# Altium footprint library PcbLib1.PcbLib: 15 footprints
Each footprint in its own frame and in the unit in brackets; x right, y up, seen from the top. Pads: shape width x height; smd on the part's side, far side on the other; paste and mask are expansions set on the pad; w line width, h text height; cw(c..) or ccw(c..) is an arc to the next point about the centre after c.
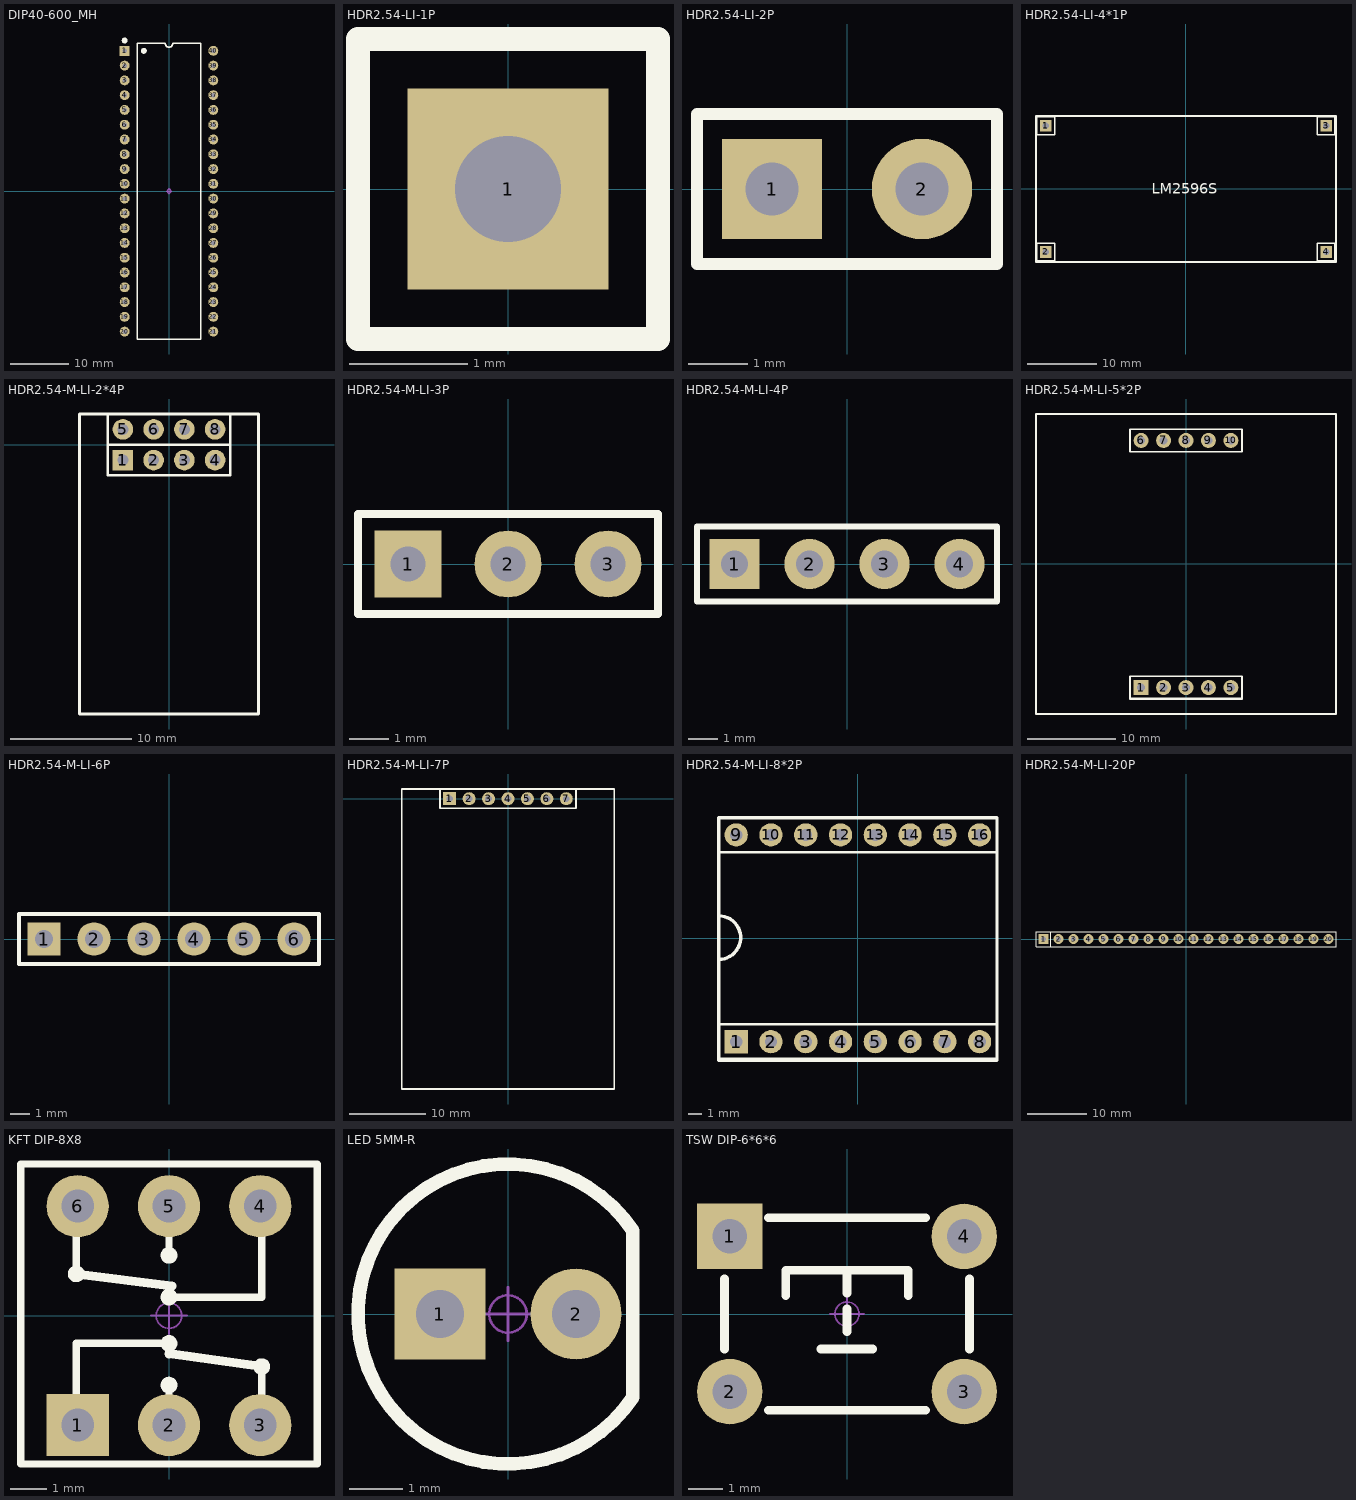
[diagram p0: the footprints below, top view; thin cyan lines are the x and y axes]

## DIP40-600_MH [mm] "带底座 52*15.2*4mm(长宽高)"
pads (40):
  rect 1.7x1.7 hole 0.8: 1(-7.62,24.13)
  round 1.7 hole 0.8: 2(-7.62,21.59) 3(-7.62,19.05) 4(-7.62,16.51) 5(-7.62,13.97) 6(-7.62,11.43) 7(-7.62,8.89) 8(-7.62,6.35) 9(-7.62,3.81) 10(-7.62,1.27) 11(-7.62,-1.27) 12(-7.62,-3.81) 13(-7.62,-6.35) 14(-7.62,-8.89) 15(-7.62,-11.43) 16(-7.62,-13.97) 17(-7.62,-16.51) 18(-7.62,-19.05) 19(-7.62,-21.59) 20(-7.62,-24.13) 21(7.62,-24.13) 22(7.62,-21.59) 23(7.62,-19.05) 24(7.62,-16.51) 25(7.62,-13.97) 26(7.62,-11.43) 27(7.62,-8.89) 28(7.62,-6.35) 29(7.62,-3.81) 30(7.62,-1.27) 31(7.62,1.27) 32(7.62,3.81) 33(7.62,6.35) 34(7.62,8.89) 35(7.62,11.43) 36(7.62,13.97) 37(7.62,16.51) 38(7.62,19.05) 39(7.62,21.59) 40(7.62,24.13)
Top Overlay:
  circle w0.508: c-4.318,24.13 r0.254
  circle w0.508: c-7.62,25.908 r0.254
  lines w0.254: -5.461,-25.4 5.461,-25.4 5.461,25.4 0.635,25.4 cw(c0,25.4) -0.635,25.4 -5.461,25.4 -5.461,-25.4
Mechanical 15:
  circle w0.05: c0,0 r0.35
  lines w0.05: -0.5,0 0.5,0 ; 0,-0.5 0,0.5
3D body "DIP-MH40-600.STEP": height 5.2, standoff -3, extent -8.9,-25.3 8.9,25.3
3D body "DIP40-600.STEP": height 8.3, standoff 0.4, extent -7.78,-26.176 7.78,26.176

## HDR2.54-LI-1P [mm] "封装库来自淘宝卖家 ID：黄晶宝石"
pads (1):
  rect 1.7x1.7 hole 0.9: 1(0,0)
Top Overlay:
  lines w0.2: -1.27,-1.27 -1.27,1.27 1.27,1.27 1.27,-1.27 -1.27,-1.27
3D body "HDR2.54-1P.STEP": height 8.5, standoff -3, extent -1.27,-1.27 1.27,1.27

## HDR2.54-LI-2P [mm] "封装库来自淘宝卖家 ID：黄晶宝石"
pads (2):
  rect 1.7x1.7 hole 0.9: 1(-1.27,0)
  round 1.7 hole 0.9: 2(1.27,0)
Top Overlay:
  lines w0.2: -2.54,-1.27 -2.54,1.27 2.54,1.27 2.54,-1.27 -2.54,-1.27
3D body "HDR2.54-1P.STEP": height 8.5, standoff -3, extent 0,-1.27 2.54,1.27
3D body "HDR2.54-1P.STEP": height 8.5, standoff -3, extent -2.54,-1.27 0,1.27

## HDR2.54-LI-4*1P [mm]
pads (4):
  rect 1.7x1.7 hole 0.9: 1(-20.193,9.08) 2(-20.193,-9.08) 3(20.193,9.08) 4(20.193,-9.08)
Top Overlay:
  lines w0.2: -21.463,-10.351 -18.923,-10.351 -18.923,-7.81 -21.463,-7.81 -21.463,-10.351 ; -21.463,7.81 -21.463,10.351 -18.923,10.351 -18.923,7.81 -21.463,7.81 ; 18.923,-10.351 21.463,-10.351 21.463,-7.81 18.923,-7.81 18.923,-10.351 ; 18.923,7.81 21.463,7.81 21.463,10.351 18.923,10.351 18.923,7.81
  lines w0.254: -21.59,-10.523 21.61,-10.523 21.61,10.477 -21.59,10.477 -21.59,-10.523
  text "LM2596S" at -4.953,-0.699 h1.52
3D body "HDR2.54-1P.STEP": height 8.5, standoff -3, extent 18.923,7.81 21.463,10.351
3D body "HDR2.54-1P.STEP": height 8.5, standoff -3, extent 18.923,-10.351 21.463,-7.81
3D body "HDR2.54-1P.STEP": height 8.5, standoff -3, extent -21.463,-10.351 -18.923,-7.81
3D body "HDR2.54-1P.STEP": height 8.5, standoff -3, extent -21.463,7.81 -18.923,10.351

## HDR2.54-M-LI-2*4P [mm]
pads (8):
  rect 1.7x1.7 hole 0.9: 1(-3.81,-1.27)
  round 1.7 hole 0.9: 2(-1.27,-1.27) 3(1.27,-1.27) 4(3.81,-1.27) 5(-3.81,1.27) 6(-1.27,1.27) 7(1.27,1.27) 8(3.81,1.27)
Top Overlay:
  lines w0.2: -5.08,0 5.08,0 ; -5.08,0 -5.08,2.54 5.08,2.54 5.08,0 ; -5.08,0 -5.08,-2.54 5.08,-2.54 5.08,0 ; -5.08,0 5.08,0
  lines w0.254: -7.4,-22.26 -7.4,2.54 0,2.54 7.4,2.54 7.4,-22.26 -7.4,-22.26
3D body "HDR2.54-1P_M.STEP": height 8.5, standoff -3, extent 0,0 2.54,2.54
3D body "HDR2.54-1P_M.STEP": height 8.5, standoff -3, extent 2.54,0 5.08,2.54
3D body "HDR2.54-1P_M.STEP": height 8.5, standoff -3, extent -5.08,0 -2.54,2.54
3D body "HDR2.54-1P_M.STEP": height 8.5, standoff -3, extent -2.54,0 0,2.54
3D body "HDR2.54-1P_M.STEP": height 8.5, standoff -3, extent -2.54,-2.54 0,0
3D body "HDR2.54-1P_M.STEP": height 8.5, standoff -3, extent -5.08,-2.54 -2.54,0
3D body "HDR2.54-1P_M.STEP": height 8.5, standoff -3, extent 2.54,-2.54 5.08,0
3D body "HDR2.54-1P_M.STEP": height 8.5, standoff -3, extent 0,-2.54 2.54,0

## HDR2.54-M-LI-3P [mm] "排母，3脚   淘宝ID:黄晶宝石   店铺网址:https://shop463601444.taobao.com"
pads (3):
  rect 1.7x1.7 hole 0.9: 1(-2.54,0)
  round 1.7 hole 0.9: 2(0,0) 3(2.54,0)
Top Overlay:
  lines w0.2: -3.81,-1.27 -3.81,1.27 3.81,1.27 3.81,-1.27 -3.81,-1.27
3D body "HDR2.54-1P_M.STEP": height 8.5, standoff -3, extent 1.27,-1.27 3.81,1.27
3D body "HDR2.54-1P_M.STEP": height 8.5, standoff -3, extent -3.81,-1.27 -1.27,1.27
3D body "HDR2.54-1P_M.STEP": height 8.5, standoff -3, extent -1.27,-1.27 1.27,1.27

## HDR2.54-M-LI-4P [mm] "排母，4脚  淘宝ID:黄晶宝石   店铺网址:https://shop463601444.taobao.com"
pads (4):
  rect 1.7x1.7 hole 0.9: 1(-3.81,0)
  round 1.7 hole 0.9: 2(-1.27,0) 3(1.27,0) 4(3.81,0)
Top Overlay:
  lines w0.2: -5.08,-1.27 -5.08,1.27 5.08,1.27 5.08,-1.27 -5.08,-1.27
3D body "HDR2.54-1P_M.STEP": height 8.5, standoff -3, extent -2.54,-1.27 0,1.27
3D body "HDR2.54-1P_M.STEP": height 8.5, standoff -3, extent -5.08,-1.27 -2.54,1.27
3D body "HDR2.54-1P_M.STEP": height 8.5, standoff -3, extent 2.54,-1.27 5.08,1.27
3D body "HDR2.54-1P_M.STEP": height 8.5, standoff -3, extent 0,-1.27 2.54,1.27

## HDR2.54-M-LI-5*2P [mm]
pads (10):
  rect 1.7x1.7 hole 0.9: 1(-5.08,-14)
  round 1.7 hole 0.9: 2(-2.54,-14) 3(0,-14) 4(2.54,-14) 5(5.08,-14) 6(-5.08,14) 7(-2.54,14) 8(0,14) 9(2.54,14) 10(5.08,14)
Top Overlay:
  lines w0.2: -6.35,-15.27 -6.35,-12.73 6.35,-12.73 6.35,-15.27 ; -6.35,12.73 6.35,12.73 6.35,15.27 -6.35,15.27 -6.35,12.73
  lines w0.254: -6.35,-15.27 6.35,-15.27 ; -17,-17 17,-17 17,17 -17,17 -17,-17
3D body "HDR2.54-1P_M.STEP": height 8.5, standoff -3, extent 3.81,-15.27 6.35,-12.73
3D body "HDR2.54-1P_M.STEP": height 8.5, standoff -3, extent -1.27,-15.27 1.27,-12.73
3D body "HDR2.54-1P_M.STEP": height 8.5, standoff -3, extent 1.27,-15.27 3.81,-12.73
3D body "HDR2.54-1P_M.STEP": height 8.5, standoff -3, extent -6.35,-15.27 -3.81,-12.73
3D body "HDR2.54-1P_M.STEP": height 8.5, standoff -3, extent -3.81,-15.27 -1.27,-12.73
3D body "HDR2.54-1P_M.STEP": height 8.5, standoff -3, extent -3.81,12.73 -1.27,15.27
3D body "HDR2.54-1P_M.STEP": height 8.5, standoff -3, extent -6.35,12.73 -3.81,15.27
3D body "HDR2.54-1P_M.STEP": height 8.5, standoff -3, extent 1.27,12.73 3.81,15.27
3D body "HDR2.54-1P_M.STEP": height 8.5, standoff -3, extent -1.27,12.73 1.27,15.27
3D body "HDR2.54-1P_M.STEP": height 8.5, standoff -3, extent 3.81,12.73 6.35,15.27

## HDR2.54-M-LI-6P [mm] "排母，6脚  淘宝ID:黄晶宝石   店铺网址:https://shop463601444.taobao.com"
pads (6):
  rect 1.7x1.7 hole 0.9: 1(-6.35,0)
  round 1.7 hole 0.9: 2(-3.81,0) 3(-1.27,0) 4(1.27,0) 5(3.81,0) 6(6.35,0)
Top Overlay:
  lines w0.2: -7.62,-1.27 7.62,-1.27 7.62,1.27 -7.62,1.27 -7.62,-1.27
3D body "HDR2.54-1P_M.STEP": height 8.5, standoff -3, extent -2.54,-1.27 0,1.27
3D body "HDR2.54-1P_M.STEP": height 8.5, standoff -3, extent -7.62,-1.27 -5.08,1.27
3D body "HDR2.54-1P_M.STEP": height 8.5, standoff -3, extent -5.08,-1.27 -2.54,1.27
3D body "HDR2.54-1P_M.STEP": height 8.5, standoff -3, extent 5.08,-1.27 7.62,1.27
3D body "HDR2.54-1P_M.STEP": height 8.5, standoff -3, extent 0,-1.27 2.54,1.27
3D body "HDR2.54-1P_M.STEP": height 8.5, standoff -3, extent 2.54,-1.27 5.08,1.27

## HDR2.54-M-LI-7P [mm] "排母，7脚"
pads (7):
  rect 1.7x1.7 hole 0.9: 1(-7.62,0)
  round 1.7 hole 0.9: 2(-5.08,0) 3(-2.54,0) 4(0,0) 5(2.54,0) 6(5.08,0) 7(7.62,0)
Top Overlay:
  lines w0.2: -8.89,-1.27 8.89,-1.27 8.89,1.27 -8.89,1.27 -8.89,-1.27
  lines w0.254: -13.89,-37.95 13.89,-37.95 13.89,1.27 -13.89,1.27 -13.89,-37.95
3D body "HDR2.54-1P_M.STEP": height 8.5, standoff -3, extent -3.81,-1.27 -1.27,1.27
3D body "HDR2.54-1P_M.STEP": height 8.5, standoff -3, extent -8.89,-1.27 -6.35,1.27
3D body "HDR2.54-1P_M.STEP": height 8.5, standoff -3, extent -6.35,-1.27 -3.81,1.27
3D body "HDR2.54-1P_M.STEP": height 8.5, standoff -3, extent 3.81,-1.27 6.35,1.27
3D body "HDR2.54-1P_M.STEP": height 8.5, standoff -3, extent -1.27,-1.27 1.27,1.27
3D body "HDR2.54-1P_M.STEP": height 8.5, standoff -3, extent 1.27,-1.27 3.81,1.27
3D body "HDR2.54-1P_M.STEP": height 8.5, standoff -3, extent 6.35,-1.27 8.89,1.27

## HDR2.54-M-LI-8*2P [mm] "排母，8*2脚"
pads (16):
  rect 1.7x1.7 hole 0.9: 1(-8.89,-7.55)
  round 1.7 hole 0.9: 2(-6.35,-7.55) 3(-3.81,-7.55) 4(-1.27,-7.55) 5(1.27,-7.55) 6(3.81,-7.55) 7(6.35,-7.55) 8(8.89,-7.55) 9(-8.89,7.55) 10(-6.35,7.55) 11(-3.81,7.55) 12(-1.27,7.55) 13(1.27,7.55) 14(3.81,7.55) 15(6.35,7.55) 16(8.89,7.55)
Top Overlay:
  lines w0.2: -10.16,-8.82 -10.16,-6.28 10.16,-6.28 10.16,-8.82 -10.16,-8.82 ; -10.16,6.28 10.16,6.28 10.16,8.82 -10.16,8.82 -10.16,6.28
  lines w0.254: -10.16,-1.543 ccw(c-10.16,0.05) -10.16,1.643 ; -10.16,-8.923 0,-8.923 10.16,-8.923 10.16,8.82 -10.16,8.82 -10.16,-8.923
3D body "HDR2.54-1P_M.STEP": height 8.5, standoff -3, extent 7.62,6.28 10.16,8.82
3D body "HDR2.54-1P_M.STEP": height 8.5, standoff -3, extent -5.08,6.28 -2.54,8.82
3D body "HDR2.54-1P_M.STEP": height 8.5, standoff -3, extent -10.16,6.28 -7.62,8.82
3D body "HDR2.54-1P_M.STEP": height 8.5, standoff -3, extent -7.62,6.28 -5.08,8.82
3D body "HDR2.54-1P_M.STEP": height 8.5, standoff -3, extent 2.54,6.28 5.08,8.82
3D body "HDR2.54-1P_M.STEP": height 8.5, standoff -3, extent -2.54,6.28 0,8.82
3D body "HDR2.54-1P_M.STEP": height 8.5, standoff -3, extent 0,6.28 2.54,8.82
3D body "HDR2.54-1P_M.STEP": height 8.5, standoff -3, extent 5.08,6.28 7.62,8.82
3D body "HDR2.54-1P_M.STEP": height 8.5, standoff -3, extent 5.08,-8.82 7.62,-6.28
3D body "HDR2.54-1P_M.STEP": height 8.5, standoff -3, extent 0,-8.82 2.54,-6.28
3D body "HDR2.54-1P_M.STEP": height 8.5, standoff -3, extent -2.54,-8.82 0,-6.28
3D body "HDR2.54-1P_M.STEP": height 8.5, standoff -3, extent 2.54,-8.82 5.08,-6.28
3D body "HDR2.54-1P_M.STEP": height 8.5, standoff -3, extent -7.62,-8.82 -5.08,-6.28
3D body "HDR2.54-1P_M.STEP": height 8.5, standoff -3, extent -10.16,-8.82 -7.62,-6.28
3D body "HDR2.54-1P_M.STEP": height 8.5, standoff -3, extent -5.08,-8.82 -2.54,-6.28
3D body "HDR2.54-1P_M.STEP": height 8.5, standoff -3, extent 7.62,-8.82 10.16,-6.28

## HDR2.54-M-LI-20P [mm] "排母，20脚"
pads (20):
  rect 1.7x1.7 hole 0.9: 1(-24.13,0)
  round 1.7 hole 0.9: 2(-21.59,0) 3(-19.05,0) 4(-16.51,0) 5(-13.97,0) 6(-11.43,0) 7(-8.89,0) 8(-6.35,0) 9(-3.81,0) 10(-1.27,0) 11(1.27,0) 12(3.81,0) 13(6.35,0) 14(8.89,0) 15(11.43,0) 16(13.97,0)
  round 1.7 hole 0.762: 17(16.51,0) 18(19.05,0) 19(21.59,0) 20(24.13,0)
Top Overlay:
  lines w0.2: -22.88,-1.25 -22.88,1.25 ; -25.4,-1.27 25.4,-1.27 25.4,1.27 -23.495,1.27 -25.4,1.27 -25.4,-1.27
3D body "HDR2.54-1P_M.STEP": height 8.5, standoff -3, extent -15.24,-1.27 -12.7,1.27
3D body "HDR2.54-1P_M.STEP": height 8.5, standoff -3, extent -17.78,-1.27 -15.24,1.27
3D body "HDR2.54-1P_M.STEP": height 8.5, standoff -3, extent -20.32,-1.27 -17.78,1.27
3D body "HDR2.54-1P_M.STEP": height 8.5, standoff -3, extent -22.86,-1.27 -20.32,1.27
3D body "HDR2.54-1P_M.STEP": height 8.5, standoff -3, extent -25.4,-1.27 -22.86,1.27
3D body "HDR2.54-1P_M.STEP": height 8.5, standoff -3, extent -2.54,-1.27 0,1.27
3D body "HDR2.54-1P_M.STEP": height 8.5, standoff -3, extent -5.08,-1.27 -2.54,1.27
3D body "HDR2.54-1P_M.STEP": height 8.5, standoff -3, extent -7.62,-1.27 -5.08,1.27
3D body "HDR2.54-1P_M.STEP": height 8.5, standoff -3, extent -10.16,-1.27 -7.62,1.27
3D body "HDR2.54-1P_M.STEP": height 8.5, standoff -3, extent -12.7,-1.27 -10.16,1.27
3D body "HDR2.54-1P_M.STEP": height 8.5, standoff -3, extent 10.16,-1.27 12.7,1.27
3D body "HDR2.54-1P_M.STEP": height 8.5, standoff -3, extent 7.62,-1.27 10.16,1.27
3D body "HDR2.54-1P_M.STEP": height 8.5, standoff -3, extent 5.08,-1.27 7.62,1.27
3D body "HDR2.54-1P_M.STEP": height 8.5, standoff -3, extent 2.54,-1.27 5.08,1.27
3D body "HDR2.54-1P_M.STEP": height 8.5, standoff -3, extent 0,-1.27 2.54,1.27
3D body "HDR2.54-1P_M.STEP": height 8.5, standoff -3, extent 22.86,-1.27 25.4,1.27
3D body "HDR2.54-1P_M.STEP": height 8.5, standoff -3, extent 20.32,-1.27 22.86,1.27
3D body "HDR2.54-1P_M.STEP": height 8.5, standoff -3, extent 17.78,-1.27 20.32,1.27
3D body "HDR2.54-1P_M.STEP": height 8.5, standoff -3, extent 15.24,-1.27 17.78,1.27
3D body "HDR2.54-1P_M.STEP": height 8.5, standoff -3, extent 12.7,-1.27 15.24,1.27

## KFT DIP-8X8 [mm] "自锁开关，规格：8*8mm      淘宝ID:黄晶宝石"
pads (6):
  rect 1.7x1.7 hole 0.9: 1(-2.5,-3)
  round 1.7 hole 0.9: 2(0,-3) 3(2.5,-3) 4(2.5,3) 5(0,3) 6(-2.5,3)
Top Overlay:
  circle w0.254: c-2.54,1.143 r0.102
  circle w0.254: c0,1.651 r0.102
  circle w0.254: c0,-1.905 r0.102
  circle w0.254: c2.54,-1.397 r0.102
  circle w0.254: c0,0.508 r0.102
  circle w0.254: c0,-0.762 r0.102
  lines w0.2: -4.064,-4.064 4.064,-4.064 4.064,4.153 -4.064,4.153 -4.064,-4.064
  lines w0.203: -2.54,-3.048 -2.54,-0.762 0,-0.762 ; -2.54,1.143 -2.54,2.794 ; 0,-3.048 0,-1.771 ; 0,0.508 2.54,0.508 2.54,2.794 ; 0,1.6 0,2.794 ; 2.54,-3.048 2.54,-1.397
  lines w0.254: -2.54,1.143 0.076,0.813 ; 0,-1.041 2.54,-1.397
Mechanical 15:
  circle w0.05: c0,0 r0.35
  lines w0.05: -0.5,0 0.5,0 ; 0,-0.5 0,0.5
3D body "SLSW 8x8.STEP": height 13.1, standoff -3.2, extent -3.949,-3.949 4.051,4.051

## LED 5MM-R [mm] "红色5mm直插LED"
height 10.16
pads (2):
  rect 1.7x1.7 hole 0.9: 1(-1.27,0)
  round 1.7 hole 0.9: 2(1.27,0)
Top Overlay:
  lines w0.254: 2.33,-1.553 cw(c0,0) 2.33,1.553 2.33,-1.553
Mechanical 15:
  circle w0.05: c0,0 r0.35
  lines w0.05: -0.5,0 0.5,0 ; 0,-0.5 0,0.5
3D body "LED 5mm-R.STEP": height 4.5, standoff -3.45, extent -1.983,-0.795 2.076,0.805
3D body "LED 5mm玻璃罩.STEP": height 8.75, standoff 0.05, extent -2.85,-2.85 2.454,2.85

## TSW DIP-6*6*6 [mm] "6*6*6mm"
pads (4):
  rect 1.9x1.9 hole 1: 1(-3.4,2.25)
  round 1.9 hole 1: 2(-3.4,-2.25) 3(3.4,-2.25) 4(3.4,2.25)
Top Overlay:
  lines w0.254: -3.556,-1.016 -3.556,1.016 ; -2.286,-2.794 2.286,-2.794 ; -2.286,2.794 2.286,2.794 ; -1.778,0.533 -1.778,1.27 1.778,1.27 1.778,0.533 ; -0.762,-1.016 0.737,-1.016 ; 0,-0.508 0,0.152 ; 0,0.61 0,1.27 ; 3.556,-1.016 3.556,1.016
Bottom Overlay:
  lines w0.254: -2.286,-2.286 2.286,-2.286 ; -2.286,2.286 2.286,2.286
Mechanical 15:
  circle w0.05: c0,0 r0.35
  lines w0.05: -0.5,0 0.5,0 ; 0,-0.5 0,0.5
3D body "TSW DIP-6x6x6.STEP": height 5.95, standoff -3.45, extent -4.106,-3 4.106,3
